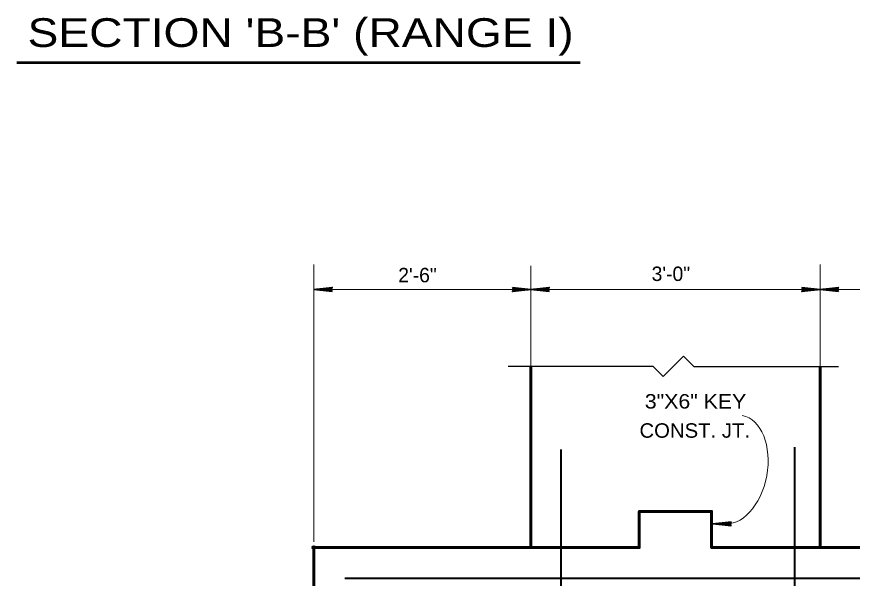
# Model space of a CAD drawing. Extents: x 14.14 to 17.34, y -1.61 to 0.38.
# Drawn here: x 15.5102 to 15.9916, y -0.4318 to -0.1078 of the extents above; entities that cross this region are included whole.
import ezdxf

# ---------------------------------------------------------------- set-up
doc = ezdxf.new("R2010")
doc.units = 0
doc.header["$LTSCALE"] = 0.0033
doc.header["$PDMODE"] = 32
doc.header["$PDSIZE"] = 0.00165
doc.layers.add('1', color=7, linetype='Continuous', lineweight=40)

msp = doc.modelspace()

# ---------------------------------------------------------------- linework, layer by layer
at = {"layer": '1', "lineweight": 53}
msp.add_line((15.510167, -0.134167), (15.83475, -0.134167), dxfattribs=at)
at = {"layer": '1', "lineweight": 13}
for p, q in [((15.681417, -0.41075), (15.681417, -0.250667)), ((15.806417, -0.309833), (15.806417, -0.251417)), ((15.973083, -0.309833), (15.973083, -0.250667)), ((15.681667, -0.265167), (16.098333, -0.265167))]:
    msp.add_line(p, q, dxfattribs=at)
at = {"layer": '1', "lineweight": 35}
for p, q in [((15.69175, -0.264083), (15.684417, -0.264917)), ((15.69175, -0.26425), (15.684417, -0.265)), ((15.69175, -0.264333), (15.684417, -0.265167)), ((15.691833, -0.2645), (15.6845, -0.26525)), ((15.796083, -0.264167), (15.803917, -0.265083)), ((15.796083, -0.264167), (15.803917, -0.265083)), ((15.796083, -0.26425), (15.803917, -0.265083)), ((15.796083, -0.264333), (15.803917, -0.265167)), ((15.796083, -0.264333), (15.803917, -0.265333)), ((15.81675, -0.264083), (15.809417, -0.264917)), ((15.81675, -0.26425), (15.809417, -0.265)), ((15.81675, -0.264333), (15.809417, -0.265167)), ((15.816833, -0.2645), (15.8095, -0.26525)), ((15.96275, -0.264167), (15.970583, -0.265083)), ((15.96275, -0.264167), (15.970583, -0.265083)), ((15.96275, -0.26425), (15.970583, -0.265083)), ((15.96275, -0.264333), (15.970583, -0.265167)), ((15.96275, -0.264333), (15.970583, -0.265333)), ((15.983417, -0.264083), (15.976083, -0.264917)), ((15.983417, -0.26425), (15.976083, -0.265)), ((15.983417, -0.264333), (15.976083, -0.265167)), ((15.9835, -0.2645), (15.976167, -0.26525)), ((15.692, -0.265167), (15.681417, -0.265167)), ((15.69175, -0.266), (15.683917, -0.265)), ((15.69175, -0.266), (15.683917, -0.265167)), ((15.69175, -0.266167), (15.683917, -0.26525)), ((15.69175, -0.266167), (15.683917, -0.26525)), ((15.69175, -0.266083), (15.683917, -0.26525)), ((15.795833, -0.265167), (15.806417, -0.265167)), ((15.796, -0.265833), (15.803333, -0.265083)), ((15.796083, -0.266), (15.803417, -0.265167)), ((15.796083, -0.266083), (15.803417, -0.265333)), ((15.796083, -0.26625), (15.803417, -0.265417)), ((15.817, -0.265167), (15.806417, -0.265167)), ((15.81675, -0.266), (15.808917, -0.265)), ((15.81675, -0.266), (15.808917, -0.265167)), ((15.81675, -0.266167), (15.808917, -0.26525)), ((15.81675, -0.266167), (15.808917, -0.26525)), ((15.81675, -0.266083), (15.808917, -0.26525)), ((15.9625, -0.265167), (15.973083, -0.265167)), ((15.962667, -0.265833), (15.97, -0.265083)), ((15.96275, -0.266), (15.970083, -0.265167)), ((15.96275, -0.266083), (15.970083, -0.265333)), ((15.96275, -0.26625), (15.970083, -0.265417)), ((15.983667, -0.265167), (15.973083, -0.265167)), ((15.983417, -0.266), (15.975583, -0.265)), ((15.983417, -0.266), (15.975583, -0.265167)), ((15.983417, -0.266167), (15.975583, -0.26525)), ((15.983417, -0.266167), (15.975583, -0.26525)), ((15.983417, -0.266083), (15.975583, -0.26525)), ((15.921583, -0.399333), (15.91425, -0.400167)), ((15.921583, -0.3995), (15.91425, -0.40025)), ((15.921583, -0.399583), (15.91425, -0.400417)), ((15.921833, -0.400417), (15.91125, -0.400417)), ((15.921583, -0.40125), (15.91375, -0.40025)), ((15.921583, -0.40125), (15.91375, -0.400417)), ((15.921583, -0.401417), (15.91375, -0.4005)), ((15.921583, -0.401417), (15.91375, -0.4005)), ((15.921583, -0.401333), (15.91375, -0.4005)), ((15.921667, -0.39975), (15.914333, -0.4005))]:
    msp.add_line(p, q, dxfattribs=at)
at = {"layer": '1'}
msp.add_line((15.69925, -0.431667), (16.080167, -0.431667), dxfattribs=at)
at = {"layer": '1', "lineweight": 35}
for points in [[(15.692, -0.26625), (15.681417, -0.265167), (15.692, -0.264), (15.691417, -0.265167)], [(15.69125, -0.26525), (15.686583, -0.265333), (15.686583, -0.26525), (15.6875, -0.26525), (15.69125, -0.265333), (15.68825, -0.265417), (15.691417, -0.2655), (15.689167, -0.265583), (15.691417, -0.265667), (15.687917, -0.265417), (15.68325, -0.26525), (15.684167, -0.265), (15.682917, -0.265), (15.69125, -0.265), (15.688833, -0.264833), (15.691417, -0.264833), (15.686083, -0.26525), (15.691417, -0.264583)], [(15.795833, -0.264083), (15.806417, -0.265167), (15.795833, -0.266333), (15.796417, -0.265167)], [(15.796583, -0.265083), (15.80125, -0.265), (15.80125, -0.265083), (15.800333, -0.265083), (15.796583, -0.265), (15.799583, -0.264917), (15.796417, -0.264833), (15.798667, -0.26475), (15.796417, -0.264667), (15.799917, -0.264917), (15.804583, -0.265083), (15.803667, -0.265333), (15.804917, -0.265333), (15.796583, -0.265333), (15.799, -0.2655), (15.796417, -0.2655), (15.80175, -0.265083), (15.796417, -0.26575)], [(15.817, -0.26625), (15.806417, -0.265167), (15.817, -0.264), (15.816417, -0.265167)], [(15.81625, -0.26525), (15.811583, -0.265333), (15.811583, -0.26525), (15.8125, -0.26525), (15.81625, -0.265333), (15.81325, -0.265417), (15.816417, -0.2655), (15.814167, -0.265583), (15.816417, -0.265667), (15.812917, -0.265417), (15.80825, -0.26525), (15.809167, -0.265), (15.807917, -0.265), (15.81625, -0.265), (15.813833, -0.264833), (15.816417, -0.264833), (15.811083, -0.26525), (15.816417, -0.264583)], [(15.9625, -0.264083), (15.973083, -0.265167), (15.9625, -0.266333), (15.963083, -0.265167)], [(15.96325, -0.265083), (15.967917, -0.265), (15.967917, -0.265083), (15.967, -0.265083), (15.96325, -0.265), (15.96625, -0.264917), (15.963083, -0.264833), (15.965333, -0.26475), (15.963083, -0.264667), (15.966583, -0.264917), (15.97125, -0.265083), (15.970333, -0.265333), (15.971583, -0.265333), (15.96325, -0.265333), (15.965667, -0.2655), (15.963083, -0.2655), (15.968417, -0.265083), (15.963083, -0.26575)], [(15.983667, -0.26625), (15.973083, -0.265167), (15.983667, -0.264), (15.983083, -0.265167)], [(15.982917, -0.26525), (15.97825, -0.265333), (15.97825, -0.26525), (15.979167, -0.26525), (15.982917, -0.265333), (15.979917, -0.265417), (15.983083, -0.2655), (15.980833, -0.265583), (15.983083, -0.265667), (15.979583, -0.265417), (15.974917, -0.26525), (15.975833, -0.265), (15.974583, -0.265), (15.982917, -0.265), (15.9805, -0.264833), (15.983083, -0.264833), (15.97775, -0.26525), (15.983083, -0.264583)], [(15.921833, -0.4015), (15.91125, -0.400417), (15.921833, -0.39925), (15.92125, -0.400417)], [(15.921083, -0.4005), (15.916417, -0.400583), (15.916417, -0.4005), (15.917333, -0.4005), (15.921083, -0.400583), (15.918083, -0.400667), (15.92125, -0.40075), (15.919, -0.400833), (15.92125, -0.400917), (15.91775, -0.400667), (15.913083, -0.4005), (15.914, -0.40025), (15.91275, -0.40025), (15.921083, -0.40025), (15.918667, -0.400083), (15.92125, -0.400083), (15.915917, -0.4005), (15.92125, -0.399833)]]:
    msp.add_lwpolyline(points, close=True, dxfattribs=at)
for points in [[(15.69125, -0.26525), (15.691667, -0.266), (15.691417, -0.26575), (15.69125, -0.265417), (15.691, -0.2655), (15.691167, -0.265833), (15.691333, -0.265083), (15.6915, -0.264583), (15.69175, -0.264167)], [(15.796583, -0.265083), (15.796167, -0.264333), (15.796417, -0.264583), (15.796583, -0.264917), (15.796833, -0.264833), (15.796667, -0.2645), (15.7965, -0.26525), (15.796333, -0.26575), (15.796083, -0.266167)], [(15.81625, -0.26525), (15.816667, -0.266), (15.816417, -0.26575), (15.81625, -0.265417), (15.816, -0.2655), (15.816167, -0.265833), (15.816333, -0.265083), (15.8165, -0.264583), (15.81675, -0.264167)], [(15.96325, -0.265083), (15.962833, -0.264333), (15.963083, -0.264583), (15.96325, -0.264917), (15.9635, -0.264833), (15.963333, -0.2645), (15.963167, -0.26525), (15.963, -0.26575), (15.96275, -0.266167)], [(15.982917, -0.26525), (15.983333, -0.266), (15.983083, -0.26575), (15.982917, -0.265417), (15.982667, -0.2655), (15.982833, -0.265833), (15.983, -0.265083), (15.983167, -0.264583), (15.983417, -0.264167)], [(15.921083, -0.4005), (15.9215, -0.40125), (15.92125, -0.401), (15.921083, -0.400667), (15.920833, -0.40075), (15.921, -0.401083), (15.921167, -0.400333), (15.921333, -0.399833), (15.921583, -0.399417)]]:
    msp.add_lwpolyline(points, dxfattribs=at)
at = {"layer": '1', "lineweight": 25}
msp.add_lwpolyline([(15.793417, -0.309417), (15.87675, -0.309417), (15.882667, -0.315333), (15.894417, -0.303583), (15.900333, -0.3095), (15.983667, -0.3095)], dxfattribs=at)
at = {"layer": '1', "lineweight": 60}
for points in [[(15.681417, -0.414), (15.806417, -0.414), (15.806417, -0.309833)], [(15.973083, -0.309833), (15.973083, -0.414), (16.098083, -0.414)], [(15.806417, -0.414), (15.868917, -0.414), (15.868917, -0.393167), (15.910583, -0.393167), (15.910583, -0.414), (15.973083, -0.414)], [(15.681417, -0.414), (15.681417, -0.497333), (16.098083, -0.497333), (16.098083, -0.414)]]:
    msp.add_lwpolyline(points, dxfattribs=at)
at = {"layer": '1'}
for points in [[(15.95825, -0.356167), (15.95825, -0.469167), (16.02075, -0.469167)], [(15.761333, -0.469583), (15.823833, -0.469583), (15.823833, -0.357417)]]:
    msp.add_lwpolyline(points, dxfattribs=at)
at = {"layer": '1', "lineweight": 13}
msp.add_ellipse((15.922542, -0.369042), major_axis=(0.005708, 0.031125), ratio=0.635583, start_param=3.1415927, end_param=6.2831853, dxfattribs=at)
at = {"layer": '1'}
msp.add_point((15.681417, -0.414), dxfattribs=at)

# ---------------------------------------------------------------- texts
for s, height, width, p in [("SECTION 'B-B' (RANGE I)", 0.01658, 1.2, (15.516417, -0.12525)), ('3"X6" KEY', 0.008334, 1.1, (15.872083, -0.333833)), ('CONST. JT. ', 0.008334, 1.05, (15.869, -0.350667))]:
    msp.add_text(s, height=height, dxfattribs=dict(at, width=width)).set_placement(p)
for s, p in [('2\'-6"', (15.73, -0.261)), ('3\'-0"', (15.876, -0.26025))]:
    msp.add_text(s, height=0.008333, dxfattribs=at).set_placement(p)

doc.saveas('drawing.dxf')
